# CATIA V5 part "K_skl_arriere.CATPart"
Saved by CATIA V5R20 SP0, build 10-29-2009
Part number: skl_arriere
Publications: "Axe_arriere_bati", "Axe_arriere_frein"
Bounding box of the stored display mesh (mm): x -20 to 20, y 200 to 700, z 0 to 0
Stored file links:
  G:\Khaled_CFAO_2011\SIL\SIL_GR2\ahabrial\ahabrial\Khaled\CAD_ThinkMOTION\K_skl_arriere.CATPart
  G:\Données\Ecole\IFMA\2A\Thinkmotion2\Etape18\trotinette.CATProduct
  G:\Khaled_CFAO_2011\SIL\SIL_GR2\ahabrial\ahabrial\Khaled\CAD_ThinkMOTION\K_skl_bati.CATPart
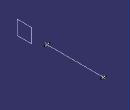
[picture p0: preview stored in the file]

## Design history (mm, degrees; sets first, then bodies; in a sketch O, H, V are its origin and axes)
Set1
  Point1: linked copy from another document
  Point2: linked copy from another document
  Plane1 "Plan_ref": linked copy from another document
Body1 (main body)
  Line1 "Droite_arriere": type PtPt, FirstPoint Point1, SecondPoint Point2
  Line2 "Axe_arriere_bati": type Normal, RefPoint Point1, RefSkin Plane1, Start -20, End 20
  Line3 "Axe_arriere_frein": type Normal, RefPoint Point2, RefSkin Plane1, Start -20, End 20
